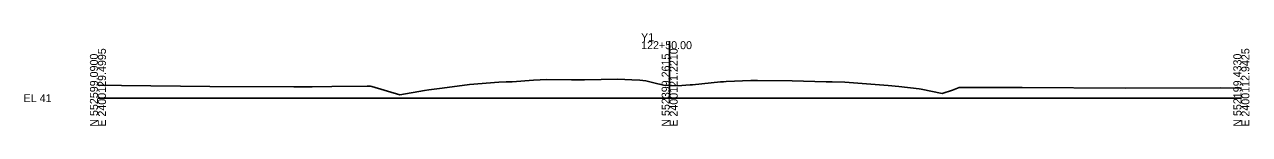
# Model space of a CAD drawing. Extents: x 14392 to 39270, y 114194 to 133492.
# Drawn here: x 24822.7 to 25251.2, y 123338.7 to 123371.1 of the extents above; entities that cross this region are included whole.
import ezdxf

# ---------------------------------------------------------------- set-up
doc = ezdxf.new("R2010")
doc.units = 0
doc.layers.add('Old_Level_60', color=7, linetype='Continuous')
doc.layers.add('Old_Level_63', color=7, linetype='Continuous')

msp = doc.modelspace()

# ---------------------------------------------------------------- linework, layer by layer
at = {"layer": 'Old_Level_60'}
for p, q in [((24978.39, 123353.18), (24988.58, 123353.95)), ((24988.58, 123353.95), (24991.19, 123354.06)), ((24991.19, 123354.06), (24993.22, 123354.13)), ((24993.22, 123354.13), (25000.78, 123354.62)), ((25000.78, 123354.62), (25005.34, 123354.91)), ((25005.34, 123354.91), (25014.01, 123354.82)), ((25014.01, 123354.82), (25017.29, 123354.79)), ((25017.29, 123354.79), (25018.55, 123354.81)), ((25018.55, 123354.81), (25030.22, 123355.02)), ((25030.22, 123355.02), (25035.17, 123354.74)), ((25035.17, 123354.74), (25037.92, 123354.72)), ((25037.92, 123354.72), (25039.98, 123354.45)), ((25039.98, 123354.45), (25042.88, 123353.73)), ((25042.88, 123353.73), (25046.17, 123352.9)), ((25056.32, 123353.07), (25066.13, 123354.05)), ((25066.13, 123354.05), (25066.5, 123354.08)), ((25066.5, 123354.08), (25067.14, 123354.1)), ((25067.14, 123354.1), (25068.18, 123354.15)), ((25068.18, 123354.15), (25076.75, 123354.58)), ((25076.75, 123354.58), (25079.11, 123354.6)), ((25079.11, 123354.6), (25091.22, 123354.46)), ((25091.22, 123354.46), (25103.16, 123354.11)), ((25103.16, 123354.11), (25105.26, 123354.04)), ((25105.26, 123354.04), (25109.6, 123353.92)), ((25109.6, 123353.92), (25124.75, 123352.78)), ((24848.36, 123352.89), (24856.62, 123352.81)), ((24856.62, 123352.81), (24887.49, 123352.39)), ((24887.49, 123352.39), (24916.86, 123352.34)), ((24916.86, 123352.34), (24923.33, 123352.32)), ((24923.33, 123352.32), (24930.22, 123352.44)), ((24930.22, 123352.44), (24942.53, 123352.58)), ((24942.53, 123352.58), (24943.72, 123352.59)), ((24943.72, 123352.59), (24944.19, 123352.46)), ((24944.19, 123352.46), (24953.94, 123349.48)), ((24953.94, 123349.48), (24962.58, 123351)), ((24962.58, 123351), (24964.09, 123351.28)), ((24964.09, 123351.28), (24968.78, 123351.89)), ((24968.78, 123351.89), (24978.39, 123353.18)), ((25046.17, 123352.9), (25048.36, 123352.82)), ((25048.36, 123352.82), (25048.97, 123352.8)), ((25048.97, 123352.8), (25051.16, 123352.7)), ((25051.16, 123352.7), (25055.54, 123353)), ((25055.54, 123353), (25056.32, 123353.07)), ((25124.75, 123352.78), (25128.56, 123352.44)), ((25128.56, 123352.44), (25135.63, 123351.64)), ((25135.63, 123351.64), (25136.4, 123351.56)), ((25136.4, 123351.56), (25143.75, 123349.96)), ((25143.75, 123349.96), (25147.26, 123351.19)), ((25147.26, 123351.19), (25149.68, 123352.14)), ((25149.68, 123352.14), (25162.7, 123352.09)), ((25162.7, 123352.09), (25167.8, 123352.06)), ((25167.8, 123352.06), (25171.62, 123352.04)), ((25171.62, 123352.04), (25207.76, 123351.92)), ((25207.76, 123351.92), (25241.04, 123351.94)), ((25241.04, 123351.94), (25247.81, 123351.91)), ((25247.81, 123351.91), (25248.36, 123351.91))]:
    msp.add_line(p, q, dxfattribs=at)
at = {"layer": 'Old_Level_63'}
for p, q in [((25048.36, 123348.36), (25048.36, 123368.33)), ((24848.36, 123348.36), (25048.36, 123348.36)), ((25048.36, 123348.36), (25248.36, 123348.36))]:
    msp.add_line(p, q, dxfattribs=at)

# ---------------------------------------------------------------- texts
for s, p in [('Y1', (25038.36, 123368.33)), ('122+50.00', (25038.37, 123365.53)), ('EL 41', (24822.36, 123346.96))]:
    msp.add_text(s, height=2.8, dxfattribs=at).set_placement(p)
for s, p in [('N 552599.0900', (24848.36, 123338.36)), ('E 2400129.4995', (24851.16, 123338.36)), ('N 552399.2615', (25048.36, 123338.36)), ('E 2400121.2210', (25051.16, 123338.36)), ('N 552199.4330', (25248.36, 123338.36)), ('E 2400112.9425', (25251.16, 123338.36))]:
    msp.add_text(s, height=2.8, rotation=90, dxfattribs=at).set_placement(p)

doc.saveas('drawing.dxf')
